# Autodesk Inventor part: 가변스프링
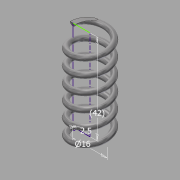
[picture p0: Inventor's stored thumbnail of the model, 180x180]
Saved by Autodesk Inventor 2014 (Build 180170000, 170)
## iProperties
Created: 2015-07
Part Number: 가변스프링
Material: 강철, 탄소
Document SubType Name: Modeling
Designer: study
Mass: 11.5077 g
Surface Area: 23.7555 cm^2
Volume: 1.46223 cm^3
Density: 7.87 g/cm^3
Appearance: 반연마
Author: study
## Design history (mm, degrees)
sketch "스케치2"
  geometry: L1 (0, 0)-(0, 42); L2 (0, 42)-(8, 42); L3 (8, 42)-(8, 0); L4 (8, 0)-(0, 0); C1 r 1.25 at (8, 0)
  constraints: 8 end point, 2 parallel, 1 centre point, 1 coincident, 1 perpendicular, 1 vertical
  dimensions: "d1" = 16 diameter of L3 L1; "d2" = 42 distance of L1.start L1.end (derived); "d3" = 2.5 diameter of C1
feature "코일1" pitch "d4" = 10; turns "d6" = 6; dims "d5" = 42 (= d2), "d7" = 0, angle "d8" = 90 deg, angle "d9" = 90 deg, "d10" = 0, "d11" = 0
node "작업 평면1"
sketch "스케치3"
  geometry: L1 (6.75, 0)-(9.25, 0) reference; 1 further point
  constraints: 1 horizontal alignment
extrude "돌출1" cut sketch "스케치3" stored distance "d13" = 10; taper "d14" = 0 deg
node "작업 평면2"
sketch "스케치4"
  geometry: L1 (-1.25, 0)-(1.25, 0) reference; 1 further point
  constraints: 1 horizontal alignment
extrude "돌출2" cut sketch "스케치4" stored distance "d16" = 10; taper "d17" = 0 deg
node "솔리드1"
node "절단 모서리 투영1"
node "절단 모서리 투영2"
other parameters: "d12" = 90 deg, "d15" = 90 deg
